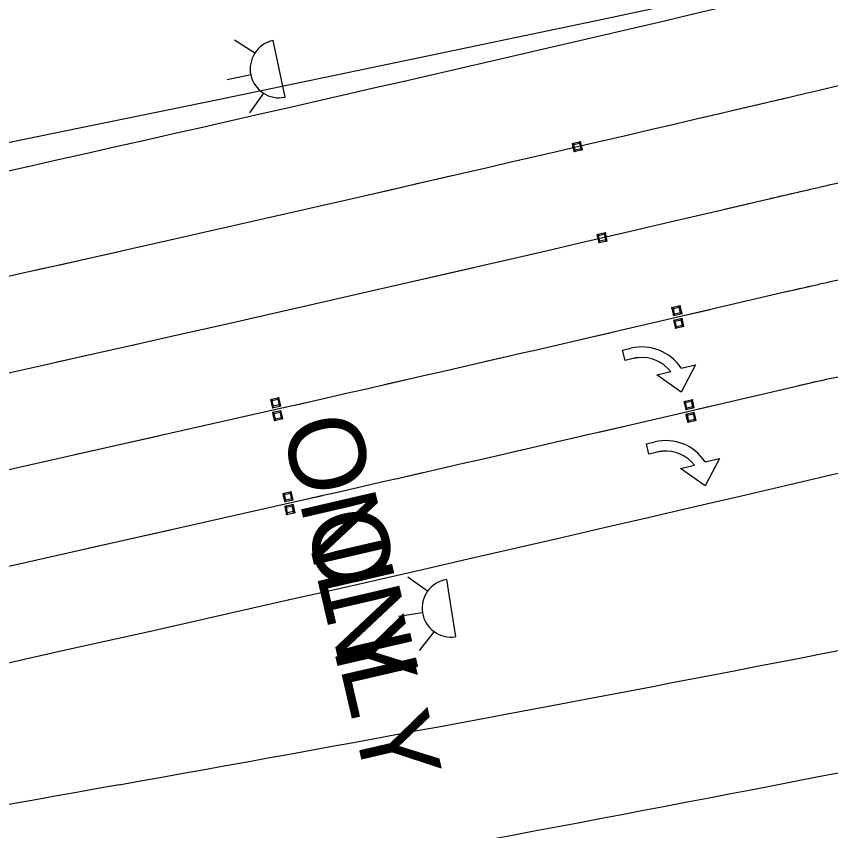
# Model space of a CAD drawing. Extents: x 2471014 to 2497726, y 6959577 to 6980268.
# Drawn here: x 2483276.3 to 2483371.3, y 6967482.9 to 6967577.9 of the extents above; entities that cross this region are included whole.
import ezdxf

# ---------------------------------------------------------------- set-up
doc = ezdxf.new("R2010")
doc.units = 0
for name, color, linetype in [('1', 7, 'Continuous'), ('13', 7, 'Continuous'), ('18', 7, 'Continuous'), ('23', 7, 'Continuous'), ('5', 7, 'Continuous'), ('59', 7, 'Continuous'), ('C-PROF-ALGN-ROAD', 7, 'Continuous'), ('Level 30', 7, 'Continuous'), ('Level 40', 7, 'Continuous'), ('p_structure fence', 7, 'Continuous'), ('p_structure wall', 7, 'Continuous'), ('PMK_Del_D-SY_SZ_TYC_CTB', 7, 'Continuous'), ('S-BRDG-BENT', 7, 'Continuous'), ('V7_25', 7, 'Continuous')]:
    doc.layers.add(name, color=color, linetype=linetype)

msp = doc.modelspace()

# ---------------------------------------------------------------- linework, layer by layer
at = {"layer": '1'}
for p, q in [((2483356.326, 6967566.135), (2483366.062, 6967568.418)), ((2483317.356, 6967557.117), (2483327.102, 6967559.354)), ((2483358.87, 6967555.433), (2483368.61, 6967557.696)), ((2483278.344, 6967548.282), (2483288.1, 6967550.474)), ((2483319.899, 6967546.414), (2483329.646, 6967548.652)), ((2483280.887, 6967537.579), (2483290.644, 6967539.771)), ((2483283.117, 6967526.806), (2483292.874, 6967528.998)), ((2483284.671, 6967515.882), (2483294.428, 6967518.072))]:
    msp.add_line(p, q, dxfattribs=at)
at = {"layer": '13'}
for centre, radius, start, end in [((2481420.533, 6975842.771), 8488, 280.221003, 283.1975649), ((2482422, 6972358.862), 4947, 280.085516, 281.955055), ((2483792.473, 6964653.793), 2879, 100.085516, 103.310254)]:
    msp.add_arc(centre, radius, start, end, dxfattribs=at)
at = {"layer": '18'}
for centre, radius, start, end in [((2481420.533, 6975842.771), 8544, 278.5401661, 283.1979685), ((2482422, 6972358.862), 4961, 280.085516, 282.003269)]:
    msp.add_arc(centre, radius, start, end, dxfattribs=at)
at = {"layer": '23'}
for p, q in [((2483341.112, 6967563.101), (2483342.099, 6967563.33)), ((2483341.311, 6967562.984), (2483341.112, 6967563.101)), ((2483341.112, 6967563.101), (2483341.172, 6967562.839)), ((2483342.099, 6967563.33), (2483341.969, 6967563.136)), ((2483341.969, 6967563.136), (2483342.001, 6967562.999)), ((2483342.327, 6967562.343), (2483342.099, 6967563.33)), ((2483341.172, 6967562.839), (2483341.34, 6967562.114)), ((2483341.464, 6967562.325), (2483341.311, 6967562.984)), ((2483342.327, 6967562.343), (2483341.34, 6967562.114)), ((2483341.34, 6967562.114), (2483341.464, 6967562.325)), ((2483342.001, 6967562.999), (2483342.122, 6967562.478)), ((2483342.122, 6967562.478), (2483342.327, 6967562.343)), ((2483344.001, 6967552.479), (2483344.989, 6967552.708)), ((2483344.989, 6967552.708), (2483344.859, 6967552.515)), ((2483345.216, 6967551.722), (2483344.989, 6967552.708)), ((2483344.2, 6967552.362), (2483344.001, 6967552.479)), ((2483344.001, 6967552.479), (2483344.062, 6967552.217)), ((2483344.062, 6967552.217), (2483344.23, 6967551.493)), ((2483344.353, 6967551.703), (2483344.2, 6967552.362)), ((2483345.216, 6967551.722), (2483344.23, 6967551.493)), ((2483344.23, 6967551.493), (2483344.353, 6967551.703)), ((2483344.859, 6967552.515), (2483344.891, 6967552.377)), ((2483344.891, 6967552.377), (2483345.012, 6967551.856)), ((2483345.012, 6967551.856), (2483345.216, 6967551.722)), ((2483352.718, 6967543.982), (2483353.705, 6967544.212)), ((2483353.705, 6967544.212), (2483353.576, 6967544.018)), ((2483353.576, 6967544.018), (2483353.608, 6967543.88)), ((2483353.933, 6967543.225), (2483353.705, 6967544.212)), ((2483352.917, 6967543.865), (2483352.718, 6967543.982)), ((2483352.718, 6967543.982), (2483352.779, 6967543.72)), ((2483352.779, 6967543.72), (2483352.947, 6967542.996)), ((2483353.07, 6967543.206), (2483352.917, 6967543.865)), ((2483353.933, 6967543.225), (2483352.947, 6967542.996)), ((2483352.947, 6967542.996), (2483353.07, 6967543.206)), ((2483353.608, 6967543.88), (2483353.729, 6967543.359)), ((2483353.729, 6967543.359), (2483353.933, 6967543.225)), ((2483352.941, 6967542.494), (2483353.929, 6967542.724)), ((2483353.141, 6967542.377), (2483352.941, 6967542.494)), ((2483352.941, 6967542.494), (2483353.002, 6967542.232)), ((2483353.002, 6967542.232), (2483353.171, 6967541.508)), ((2483353.294, 6967541.718), (2483353.141, 6967542.377)), ((2483353.929, 6967542.724), (2483353.799, 6967542.53)), ((2483353.799, 6967542.53), (2483353.831, 6967542.392)), ((2483353.831, 6967542.392), (2483353.953, 6967541.871)), ((2483354.157, 6967541.737), (2483353.929, 6967542.724)), ((2483354.157, 6967541.737), (2483353.171, 6967541.508)), ((2483353.171, 6967541.508), (2483353.294, 6967541.718)), ((2483353.953, 6967541.871), (2483354.157, 6967541.737)), ((2483305.94, 6967533.229), (2483306.929, 6967533.454)), ((2483306.139, 6967533.111), (2483305.94, 6967533.229)), ((2483305.94, 6967533.229), (2483306, 6967532.967)), ((2483306, 6967532.967), (2483306.165, 6967532.242)), ((2483306.289, 6967532.452), (2483306.139, 6967533.111)), ((2483306.929, 6967533.454), (2483306.798, 6967533.261)), ((2483306.798, 6967533.261), (2483306.83, 6967533.123)), ((2483306.83, 6967533.123), (2483306.948, 6967532.601)), ((2483307.152, 6967532.466), (2483306.929, 6967533.454)), ((2483354.147, 6967533.02), (2483355.134, 6967533.25)), ((2483354.346, 6967532.903), (2483354.147, 6967533.02)), ((2483354.147, 6967533.02), (2483354.208, 6967532.758)), ((2483354.208, 6967532.758), (2483354.376, 6967532.034)), ((2483354.499, 6967532.244), (2483354.346, 6967532.903)), ((2483355.134, 6967533.25), (2483355.005, 6967533.056)), ((2483355.005, 6967533.056), (2483355.037, 6967532.919)), ((2483355.037, 6967532.919), (2483355.158, 6967532.398)), ((2483355.363, 6967532.263), (2483355.134, 6967533.25)), ((2483306.164, 6967531.742), (2483307.153, 6967531.966)), ((2483306.362, 6967531.624), (2483306.164, 6967531.742)), ((2483306.164, 6967531.742), (2483306.224, 6967531.48)), ((2483307.152, 6967532.466), (2483306.165, 6967532.242)), ((2483306.165, 6967532.242), (2483306.289, 6967532.452)), ((2483306.948, 6967532.601), (2483307.152, 6967532.466)), ((2483307.153, 6967531.966), (2483307.022, 6967531.774)), ((2483307.022, 6967531.774), (2483307.053, 6967531.636)), ((2483307.375, 6967530.979), (2483307.153, 6967531.966)), ((2483354.371, 6967531.532), (2483355.358, 6967531.762)), ((2483355.363, 6967532.263), (2483354.376, 6967532.034)), ((2483354.376, 6967532.034), (2483354.499, 6967532.244)), ((2483355.158, 6967532.398), (2483355.363, 6967532.263)), ((2483355.358, 6967531.762), (2483355.229, 6967531.568)), ((2483355.586, 6967530.775), (2483355.358, 6967531.762)), ((2483306.224, 6967531.48), (2483306.388, 6967530.755)), ((2483306.512, 6967530.964), (2483306.362, 6967531.624)), ((2483307.375, 6967530.979), (2483306.388, 6967530.755)), ((2483306.388, 6967530.755), (2483306.512, 6967530.964)), ((2483307.053, 6967531.636), (2483307.172, 6967531.114)), ((2483307.172, 6967531.114), (2483307.375, 6967530.979)), ((2483354.57, 6967531.415), (2483354.371, 6967531.532)), ((2483354.371, 6967531.532), (2483354.432, 6967531.27)), ((2483354.432, 6967531.27), (2483354.6, 6967530.546)), ((2483354.723, 6967530.756), (2483354.57, 6967531.415)), ((2483355.586, 6967530.775), (2483354.6, 6967530.546)), ((2483354.6, 6967530.546), (2483354.723, 6967530.756)), ((2483355.229, 6967531.568), (2483355.261, 6967531.431)), ((2483355.261, 6967531.431), (2483355.382, 6967530.91)), ((2483355.382, 6967530.91), (2483355.586, 6967530.775)), ((2483307.368, 6967522.274), (2483308.357, 6967522.498)), ((2483307.567, 6967522.156), (2483307.368, 6967522.274)), ((2483307.368, 6967522.274), (2483307.428, 6967522.012)), ((2483307.716, 6967521.496), (2483307.567, 6967522.156)), ((2483308.357, 6967522.498), (2483308.226, 6967522.305)), ((2483308.226, 6967522.305), (2483308.258, 6967522.167)), ((2483308.258, 6967522.167), (2483308.376, 6967521.646)), ((2483308.58, 6967521.51), (2483308.357, 6967522.498)), ((2483307.428, 6967522.012), (2483307.592, 6967521.286)), ((2483308.58, 6967521.51), (2483307.592, 6967521.286)), ((2483307.592, 6967521.286), (2483307.716, 6967521.496)), ((2483308.376, 6967521.646), (2483308.58, 6967521.51)), ((2483307.592, 6967520.786), (2483308.581, 6967521.011)), ((2483307.79, 6967520.668), (2483307.592, 6967520.786)), ((2483307.592, 6967520.786), (2483307.651, 6967520.524)), ((2483307.651, 6967520.524), (2483307.816, 6967519.799)), ((2483307.94, 6967520.009), (2483307.79, 6967520.668)), ((2483308.581, 6967521.011), (2483308.45, 6967520.818)), ((2483308.45, 6967520.818), (2483308.481, 6967520.68)), ((2483308.481, 6967520.68), (2483308.599, 6967520.158)), ((2483308.803, 6967520.023), (2483308.581, 6967521.011)), ((2483308.803, 6967520.023), (2483307.816, 6967519.799)), ((2483307.816, 6967519.799), (2483307.94, 6967520.009)), ((2483308.599, 6967520.158), (2483308.803, 6967520.023))]:
    msp.add_line(p, q, dxfattribs=at)
for points in [[(2483341.311, 6967562.984), (2483341.969, 6967563.136), (2483342.122, 6967562.478), (2483341.464, 6967562.325)], [(2483344.2, 6967552.362), (2483344.859, 6967552.515), (2483345.012, 6967551.856), (2483344.353, 6967551.703)], [(2483352.917, 6967543.865), (2483353.576, 6967544.018), (2483353.729, 6967543.359), (2483353.07, 6967543.206)], [(2483353.141, 6967542.377), (2483353.799, 6967542.53), (2483353.953, 6967541.871), (2483353.294, 6967541.718)], [(2483306.139, 6967533.111), (2483306.798, 6967533.261), (2483306.948, 6967532.601), (2483306.289, 6967532.452)], [(2483354.346, 6967532.903), (2483355.005, 6967533.056), (2483355.158, 6967532.398), (2483354.499, 6967532.244)], [(2483306.362, 6967531.624), (2483307.022, 6967531.774), (2483307.172, 6967531.114), (2483306.512, 6967530.964)], [(2483354.57, 6967531.415), (2483355.229, 6967531.568), (2483355.382, 6967530.91), (2483354.723, 6967530.756)], [(2483307.567, 6967522.156), (2483308.226, 6967522.305), (2483308.376, 6967521.646), (2483307.716, 6967521.496)], [(2483307.79, 6967520.668), (2483308.45, 6967520.818), (2483308.599, 6967520.158), (2483307.94, 6967520.009)]]:
    msp.add_lwpolyline(points, close=True, dxfattribs=at)
at = {"layer": '5'}
msp.add_arc((2479474.037, 6969335.883), 8460, 6.3761702, 6.3761702, dxfattribs=at)
at = {"layer": '59'}
for centre, radius, start in [((2481420.533, 6975842.771), 8522, 282.7935277), ((2481383.507, 6976000.66), 8695.172, 282.8010708)]:
    msp.add_arc(centre, radius, start, 283.1979685, dxfattribs=at)
for points in [[(2483366.245, 6967545.862), (2483367.038, 6967546.042), (2483367.831, 6967546.221), (2483368.624, 6967546.4), (2483369.417, 6967546.579), (2483370.21, 6967546.759), (2483371.003, 6967546.938), (2483371.796, 6967547.117), (2483372.589, 6967547.297), (2483373.382, 6967547.477), (2483374.174, 6967547.656), (2483374.967, 6967547.836), (2483375.76, 6967548.016), (2483376.553, 6967548.196), (2483377.345, 6967548.376), (2483378.138, 6967548.556), (2483378.931, 6967548.737), (2483379.724, 6967548.917), (2483380.516, 6967549.097), (2483381.309, 6967549.278), (2483382.102, 6967549.458), (2483382.894, 6967549.639), (2483383.687, 6967549.819), (2483384.48, 6967550), (2483385.272, 6967550.181), (2483386.065, 6967550.362), (2483386.857, 6967550.543), (2483387.65, 6967550.724), (2483388.442, 6967550.905), (2483389.235, 6967551.086), (2483390.027, 6967551.267), (2483390.82, 6967551.449), (2483391.612, 6967551.63), (2483392.405, 6967551.811), (2483393.197, 6967551.993), (2483393.99, 6967552.175), (2483394.782, 6967552.356), (2483395.574, 6967552.538), (2483396.367, 6967552.72), (2483397.159, 6967552.902), (2483397.951, 6967553.084), (2483398.744, 6967553.266), (2483399.536, 6967553.448), (2483400.328, 6967553.63), (2483401.12, 6967553.813), (2483401.913, 6967553.995), (2483402.705, 6967554.178), (2483403.497, 6967554.36), (2483404.289, 6967554.543), (2483405.082, 6967554.725), (2483405.874, 6967554.908), (2483406.666, 6967555.091), (2483407.458, 6967555.274), (2483408.25, 6967555.457), (2483409.042, 6967555.64), (2483409.834, 6967555.823), (2483410.626, 6967556.006), (2483411.418, 6967556.19), (2483412.21, 6967556.373), (2483413.002, 6967556.557), (2483413.794, 6967556.74), (2483414.586, 6967556.924), (2483415.378, 6967557.107), (2483416.17, 6967557.291), (2483416.962, 6967557.475), (2483417.754, 6967557.659), (2483418.546, 6967557.843), (2483419.338, 6967558.027), (2483420.13, 6967558.211), (2483420.921, 6967558.395), (2483421.713, 6967558.58), (2483422.505, 6967558.764), (2483423.297, 6967558.948), (2483424.089, 6967559.133), (2483424.88, 6967559.318)], [(2483368.757, 6967535.153), (2483369.552, 6967535.329), (2483370.346, 6967535.505), (2483371.141, 6967535.681), (2483371.936, 6967535.857), (2483372.731, 6967536.034), (2483373.525, 6967536.21), (2483374.32, 6967536.387), (2483375.115, 6967536.563), (2483375.909, 6967536.74), (2483376.704, 6967536.917), (2483377.498, 6967537.093), (2483378.293, 6967537.27), (2483379.088, 6967537.447), (2483379.882, 6967537.624), (2483380.677, 6967537.801), (2483381.471, 6967537.978), (2483382.266, 6967538.156), (2483383.06, 6967538.333), (2483383.855, 6967538.51), (2483384.649, 6967538.688), (2483385.444, 6967538.865), (2483386.238, 6967539.043), (2483387.032, 6967539.22), (2483387.827, 6967539.398), (2483388.621, 6967539.576), (2483389.416, 6967539.754), (2483390.21, 6967539.932), (2483391.004, 6967540.11), (2483391.799, 6967540.288), (2483392.593, 6967540.466), (2483393.387, 6967540.645), (2483394.181, 6967540.823), (2483394.976, 6967541.001), (2483395.77, 6967541.18), (2483396.564, 6967541.359), (2483397.358, 6967541.537), (2483398.153, 6967541.716), (2483398.947, 6967541.895), (2483399.741, 6967542.074), (2483400.535, 6967542.253), (2483401.329, 6967542.432), (2483402.123, 6967542.611), (2483402.917, 6967542.79), (2483403.711, 6967542.969), (2483404.506, 6967543.149), (2483405.3, 6967543.328), (2483406.094, 6967543.508), (2483406.888, 6967543.687), (2483407.682, 6967543.867), (2483408.476, 6967544.047), (2483409.27, 6967544.226), (2483410.063, 6967544.406), (2483410.857, 6967544.586), (2483411.651, 6967544.766), (2483412.445, 6967544.946), (2483413.239, 6967545.127), (2483414.033, 6967545.307), (2483414.827, 6967545.487), (2483415.621, 6967545.668), (2483416.414, 6967545.848), (2483417.208, 6967546.029), (2483418.002, 6967546.209), (2483418.796, 6967546.39), (2483419.59, 6967546.571), (2483420.383, 6967546.752), (2483421.177, 6967546.933), (2483421.971, 6967547.114), (2483422.764, 6967547.295), (2483423.558, 6967547.476), (2483424.352, 6967547.657), (2483425.145, 6967547.839), (2483425.939, 6967548.02), (2483426.733, 6967548.201), (2483427.526, 6967548.383)]]:
    msp.add_spline(points, degree=3, dxfattribs=at)
at = {"layer": 'C-PROF-ALGN-ROAD'}
msp.add_spline([(2483371.21, 6967524.43), (2483372.006, 6967524.603), (2483372.803, 6967524.776), (2483373.6, 6967524.949), (2483374.397, 6967525.122), (2483375.193, 6967525.296), (2483375.99, 6967525.469), (2483376.787, 6967525.642), (2483377.583, 6967525.816), (2483378.38, 6967525.99), (2483379.177, 6967526.163), (2483379.973, 6967526.337), (2483380.77, 6967526.511), (2483381.566, 6967526.685), (2483382.363, 6967526.859), (2483383.159, 6967527.033), (2483383.956, 6967527.207), (2483384.752, 6967527.381), (2483385.549, 6967527.555), (2483386.345, 6967527.73), (2483387.142, 6967527.904), (2483387.938, 6967528.079), (2483388.735, 6967528.253), (2483389.531, 6967528.428), (2483390.328, 6967528.603), (2483391.124, 6967528.778), (2483391.92, 6967528.953), (2483392.717, 6967529.128), (2483393.513, 6967529.303), (2483394.309, 6967529.478), (2483395.106, 6967529.653), (2483395.902, 6967529.828), (2483396.698, 6967530.004), (2483397.495, 6967530.179), (2483398.291, 6967530.355), (2483399.087, 6967530.53), (2483399.883, 6967530.706), (2483400.679, 6967530.882), (2483401.476, 6967531.057), (2483402.272, 6967531.233), (2483403.068, 6967531.409), (2483403.864, 6967531.585), (2483404.66, 6967531.762), (2483405.456, 6967531.938), (2483406.252, 6967532.114), (2483407.049, 6967532.29), (2483407.845, 6967532.467), (2483408.641, 6967532.643), (2483409.437, 6967532.82), (2483410.233, 6967532.997), (2483411.029, 6967533.173), (2483411.825, 6967533.35), (2483412.621, 6967533.527), (2483413.417, 6967533.704), (2483414.213, 6967533.881), (2483415.008, 6967534.058), (2483415.804, 6967534.235), (2483416.6, 6967534.413), (2483417.396, 6967534.59), (2483418.192, 6967534.767), (2483418.988, 6967534.945), (2483419.784, 6967535.123), (2483420.58, 6967535.3), (2483421.375, 6967535.478), (2483422.171, 6967535.656), (2483422.967, 6967535.834), (2483423.763, 6967536.012), (2483424.558, 6967536.19), (2483425.354, 6967536.368), (2483426.15, 6967536.546), (2483426.945, 6967536.724), (2483427.741, 6967536.902), (2483428.537, 6967537.081), (2483429.332, 6967537.259), (2483430.128, 6967537.438)], degree=3, dxfattribs=at)
at = {"layer": 'Level 30'}
for p, q in [((2483324.258, 6967510.881), (2483321.958, 6967512.499)), ((2483326.459, 6967512.232), (2483327.522, 6967505.567)), ((2483323.658, 6967508.368), (2483320.88, 6967507.925)), ((2483325.01, 6967506.167), (2483323.273, 6967503.955))]:
    msp.add_line(p, q, dxfattribs=at)
msp.add_arc((2483326.991, 6967508.9), 3.375, 99.05883, 279.05883, dxfattribs=at)
at = {"layer": 'Level 40'}
for p, q in [((2483365.968, 6967545.797), (2483368.894, 6967546.461)), ((2483354.283, 6967543.066), (2483357.204, 6967543.747)), ((2483342.594, 6967540.351), (2483345.516, 6967541.029)), ((2483330.901, 6967537.653), (2483333.825, 6967538.326)), ((2483319.205, 6967534.971), (2483322.129, 6967535.64)), ((2483367.524, 6967534.864), (2483370.449, 6967535.528)), ((2483307.504, 6967532.306), (2483310.43, 6967532.971)), ((2483355.838, 6967532.134), (2483358.76, 6967532.815)), ((2483344.149, 6967529.42), (2483347.072, 6967530.097)), ((2483332.456, 6967526.722), (2483335.38, 6967527.395)), ((2483320.76, 6967524.041), (2483323.684, 6967524.709)), ((2483309.06, 6967521.375), (2483311.985, 6967522.04))]:
    msp.add_line(p, q, dxfattribs=at)
at = {"layer": 'p_structure wall'}
for p, q in [((2483346.999, 6967538.984), (2483347.955, 6967539.215)), ((2483347.287, 6967537.788), (2483346.999, 6967538.984)), ((2483348.247, 6967538.02), (2483347.29, 6967537.789)), ((2483350.98, 6967536.104), (2483352.606, 6967536.496)), ((2483353.837, 6967536.889), (2483355.507, 6967537.292)), ((2483355.507, 6967537.292), (2483353.839, 6967534.102)), ((2483353.839, 6967534.102), (2483350.98, 6967536.104)), ((2483349.787, 6967528.062), (2483350.744, 6967528.293)), ((2483350.076, 6967526.866), (2483349.787, 6967528.062)), ((2483351.035, 6967527.098), (2483350.079, 6967526.867)), ((2483356.625, 6967525.967), (2483358.296, 6967526.37)), ((2483358.296, 6967526.37), (2483356.628, 6967523.18)), ((2483353.769, 6967525.182), (2483355.394, 6967525.574)), ((2483356.628, 6967523.18), (2483353.769, 6967525.182))]:
    msp.add_line(p, q, dxfattribs=at)
for centre, radius, start, end in [((2483349.245, 6967533.874), 5.494, 33.28084, 103.57026), ((2483349.245, 6967533.874), 4.264, 97.94646, 103.52921), ((2483349.245, 6967533.874), 4.264, 95.69904, 97.94646), ((2483349.245, 6967533.874), 4.264, 37.95645, 95.69904), ((2483352.033, 6967522.952), 5.494, 33.28084, 103.57026), ((2483352.033, 6967522.952), 4.264, 97.94646, 103.52921), ((2483352.033, 6967522.952), 4.264, 95.69904, 97.94646), ((2483352.033, 6967522.952), 4.264, 37.95645, 95.69904)]:
    msp.add_arc(centre, radius, start, end, dxfattribs=at)
at = {"layer": 'PMK_Del_D-SY_SZ_TYC_CTB'}
for p, q in [((2483304.111, 6967573.639), (2483301.73, 6967575.135)), ((2483307.647, 6967568.502), (2483306.238, 6967575.103)), ((2483303.642, 6967571.098), (2483300.892, 6967570.512)), ((2483305.107, 6967568.971), (2483303.488, 6967566.671))]:
    msp.add_line(p, q, dxfattribs=at)
msp.add_arc((2483306.943, 6967571.803), 3.375, 102.04564, 282.04563, dxfattribs=at)
at = {"layer": 'S-BRDG-BENT'}
msp.add_arc((2480975.493, 6978806.397), 11476, 278.5401661, 284.3749359, dxfattribs=at)
at = {"layer": 'V7_25'}
for radius, start, end in [(8500, 283.1979685, 283.8304694), (8500, 281.9844122, 283.1979685), (8511, 278.5401661, 283.1979685), (8522, 278.5401661, 282.7935277), (8533, 278.5401661, 282.7935277)]:
    msp.add_arc((2481420.533, 6975842.771), radius, start, end, dxfattribs=at)
msp.add_spline([(2483363.734, 6967556.572), (2483364.525, 6967556.754), (2483365.316, 6967556.936), (2483366.107, 6967557.118), (2483366.899, 6967557.301), (2483367.69, 6967557.483), (2483368.481, 6967557.666), (2483369.272, 6967557.848), (2483370.063, 6967558.031), (2483370.854, 6967558.214), (2483371.645, 6967558.396), (2483372.436, 6967558.579), (2483373.227, 6967558.762), (2483374.018, 6967558.945), (2483374.809, 6967559.128), (2483375.6, 6967559.311), (2483376.391, 6967559.495), (2483377.182, 6967559.678), (2483377.973, 6967559.861), (2483378.763, 6967560.045), (2483379.554, 6967560.228), (2483380.345, 6967560.412), (2483381.136, 6967560.596), (2483381.927, 6967560.78), (2483382.717, 6967560.963), (2483383.508, 6967561.147), (2483384.299, 6967561.331), (2483385.09, 6967561.515), (2483385.88, 6967561.7), (2483386.671, 6967561.884), (2483387.462, 6967562.068), (2483388.252, 6967562.252), (2483389.043, 6967562.437), (2483389.834, 6967562.621), (2483390.624, 6967562.806), (2483391.415, 6967562.991), (2483392.206, 6967563.175), (2483392.996, 6967563.36), (2483393.787, 6967563.545), (2483394.577, 6967563.73), (2483395.368, 6967563.915), (2483396.158, 6967564.1), (2483396.949, 6967564.286), (2483397.739, 6967564.471), (2483398.53, 6967564.656), (2483399.32, 6967564.842), (2483400.11, 6967565.027), (2483400.901, 6967565.213), (2483401.691, 6967565.398), (2483402.481, 6967565.584), (2483403.272, 6967565.77), (2483404.062, 6967565.956), (2483404.852, 6967566.142), (2483405.643, 6967566.328), (2483406.433, 6967566.514), (2483407.223, 6967566.7), (2483408.013, 6967566.886), (2483408.804, 6967567.073), (2483409.594, 6967567.259), (2483410.384, 6967567.446), (2483411.174, 6967567.632), (2483411.964, 6967567.819), (2483412.754, 6967568.005), (2483413.545, 6967568.192), (2483414.335, 6967568.379), (2483415.125, 6967568.566), (2483415.915, 6967568.753), (2483416.705, 6967568.94), (2483417.495, 6967569.127), (2483418.285, 6967569.315), (2483419.075, 6967569.502), (2483419.865, 6967569.689), (2483420.655, 6967569.877), (2483421.445, 6967570.064), (2483422.235, 6967570.252)], degree=3, dxfattribs=at)

# ---------------------------------------------------------------- texts
at = {"layer": 'p_structure fence'}
for p in [(2483307.193, 6967530.395), (2483309.981, 6967519.473)]:
    msp.add_text('ONLY', height=8.8984, rotation=283.06982, dxfattribs=at).set_placement(p)

doc.saveas('drawing.dxf')
